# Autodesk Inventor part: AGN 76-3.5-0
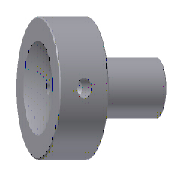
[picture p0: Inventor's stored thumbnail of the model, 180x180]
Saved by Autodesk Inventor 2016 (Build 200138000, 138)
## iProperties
IsCustomPart: 1
Created: 2015-02
Part Number: AGN 76-3.5-0
Material: DIN 1.2312
Description: Sprue Bushing
Document SubType Name: Modeling
Designer: Sandeep
Standard Revision: 1
Manufacturer: DME
Language: en-US
Size Designation: 76-3.5-0
Categories: <MemberInstance><Categories><Category DisplayName="Mold" InternalName="349578f2-f4d4-4954-8c09-8e99297a61c0" Mnemonic="MOLD"><Category DisplayName="Runners" Int
Density: 7.85 g/cm^3
Appearance: Default
Author: Sandeep
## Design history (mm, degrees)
sketch "Sketch1"
  geometry: L1 (0, -27.2)-(0, 23.2) reference; L2 (1.75, 20)-(19, 20); L3 (19, 20)-(19, 0); L4 (19, 0)-(12, 0); L5 (9, -3)-(9, -76); L6 (9, -76)-(4.264, -76); L7 (4.264, -76)-(1.75, 20); A1 r 3 centre (12, -3) between (12, 0) and (9, -3); 2 further points
  constraints: 12 end point, 3 parallel, 2 perpendicular, 2 point on circle, 2 point on line, 2 tangent, 1 centre point
  dimensions: "d0" = 18 diameter of L5 L1 (= D); "d3" = 38 diameter of L3 L1 (= d1); "d6" = 1.5 deg angle of L7 L1 (= 0.5 x Taper); "d7" = 20 distance between parallel lines of L4 L2 (= K_); "d8" = 76 distance between parallel lines of L4 L6 (= L); "d9" = 3 radius of A1 (= R3); "d62" = 3.5 diameter of point (1.75, 20) L1 (= d_); "d63" = 0 distance from line of point (1.75, 20) L2 (computed from Rd)
revolve "Revolution1" sketch "Sketch1" stored, may be unused: angle "d10" = 90 deg
sketch "Sketch2"
  geometry: L1 (0, -32.79)-(0, 56.739) reference; L2 (4.264, -76)-(1.75, 20) reference; L3 (-19, 20)-(19, 20) reference; L4 (0, 50.901)-(0, 19.901); A1 r 15.5 centre (0, 35.401) between (0, 19.901) and (0, 50.901); 2 further points
  constraints: 3 point on circle, 3 point on line, 2 end point, 1 centre point, 1 midpoint
  dimensions: "d64" = 0 distance from line of point (1.75, 20) L3 (computed from Rd); "d67" = 15.5 radius of A1 (= Rk)
revolve "Revolution2" sketch "Sketch2" stored, may be unused: angle "d13" = 90 deg
workplane "Work Plane1"
sketch "Sketch3"
  geometry: 2 further points
  constraints: 1 vertical alignment
  dimensions: "d43" = 10 distance of point (0, -10) point (0, 0) (= 0.5 x K_)
hole "Hole1" sketch "Sketch3" at (0, 0) diameter "d15" = 4 (= pd1); stored, may be unused: countersink angle "d19" = 90 deg, drill point angle "d21" = 118 deg; dims "d16" = 6, "d17" = 4, "d18" = 2, "d20" = 6 (= pl1)
chamfer "Chamfer1" distance "d22" = 0.3; stored, may be unused: second distance "d23" = 2, angle "d24" = 45 deg
sketch "Sketch4"
  geometry: L1 (0, -30.4)-(0, 42.4) reference; L2 (0, 40)-(19.5, 40); L3 (19.5, 40)-(19.5, 0); L4 (9, -76)-(0, -76); L5 (0, -76)-(0, 40); L6 (9, -3)-(9, -76); L7 (12, 0)-(19.5, 0); L8 (12, 0)-(9, -3); 2 further points
  constraints: 14 end point, 4 point on line, 2 horizontal, 2 parallel, 1 perpendicular, 1 vertical
  dimensions: "d56" = 3 distance of L7.start point (9, 0) (= R3_CS); "d57" = 3 distance of L6.start point (9, 0) (= d56); "d58" = 39 diameter of L3 L1 (= d1_CS); "d59" = 40 distance between parallel lines of L7 L2 (= K_CS); "d60" = 18 diameter of L6 L1 (= D_CS); "d61" = 76 distance between parallel lines of L7 L4 (= L_CS)
feature "RevolutionSrf1" sketch "Sketch4" dims angle "d33" = 90 deg
feature "Sculpt9"
split "Split9"
body "Solid1"
body "Srf1"
feature "Surface5"
body "Srf6"
other parameters: "L" = 76 [user parameter; used in 1 equation term], "d1" = 38 [user parameter; used in 1 equation term], "d_" = 3.5 [user parameter; used in 1 equation term], "D" = 18 [user parameter; used in 1 equation term], "K_" = 20 [user parameter; used in 2 equation terms], "R" = 0 [user parameter], "Taper" = 3 deg [user parameter; used in 1 equation term], "Rd" = 0 [user parameter; used in 2 equation terms], "R3" = 3 [user parameter; used in 1 equation term], "pd1" = 4 [user parameter; used in 1 equation term], "d1_CS" = 39 [user parameter; used in 1 equation term], "K_CS" = 40 [user parameter; used in 1 equation term], "d44" = 0, "d45" = 0, "d46" = 0, "L_CS" = 76 [user parameter; used in 1 equation term], "D_CS" = 18 [user parameter; used in 1 equation term], "pl1" = 6 [user parameter; used in 1 equation term], "R3_CS" = 3 [user parameter; used in 1 equation term], "Rk" = 15.5 [user parameter; used in 1 equation term]
